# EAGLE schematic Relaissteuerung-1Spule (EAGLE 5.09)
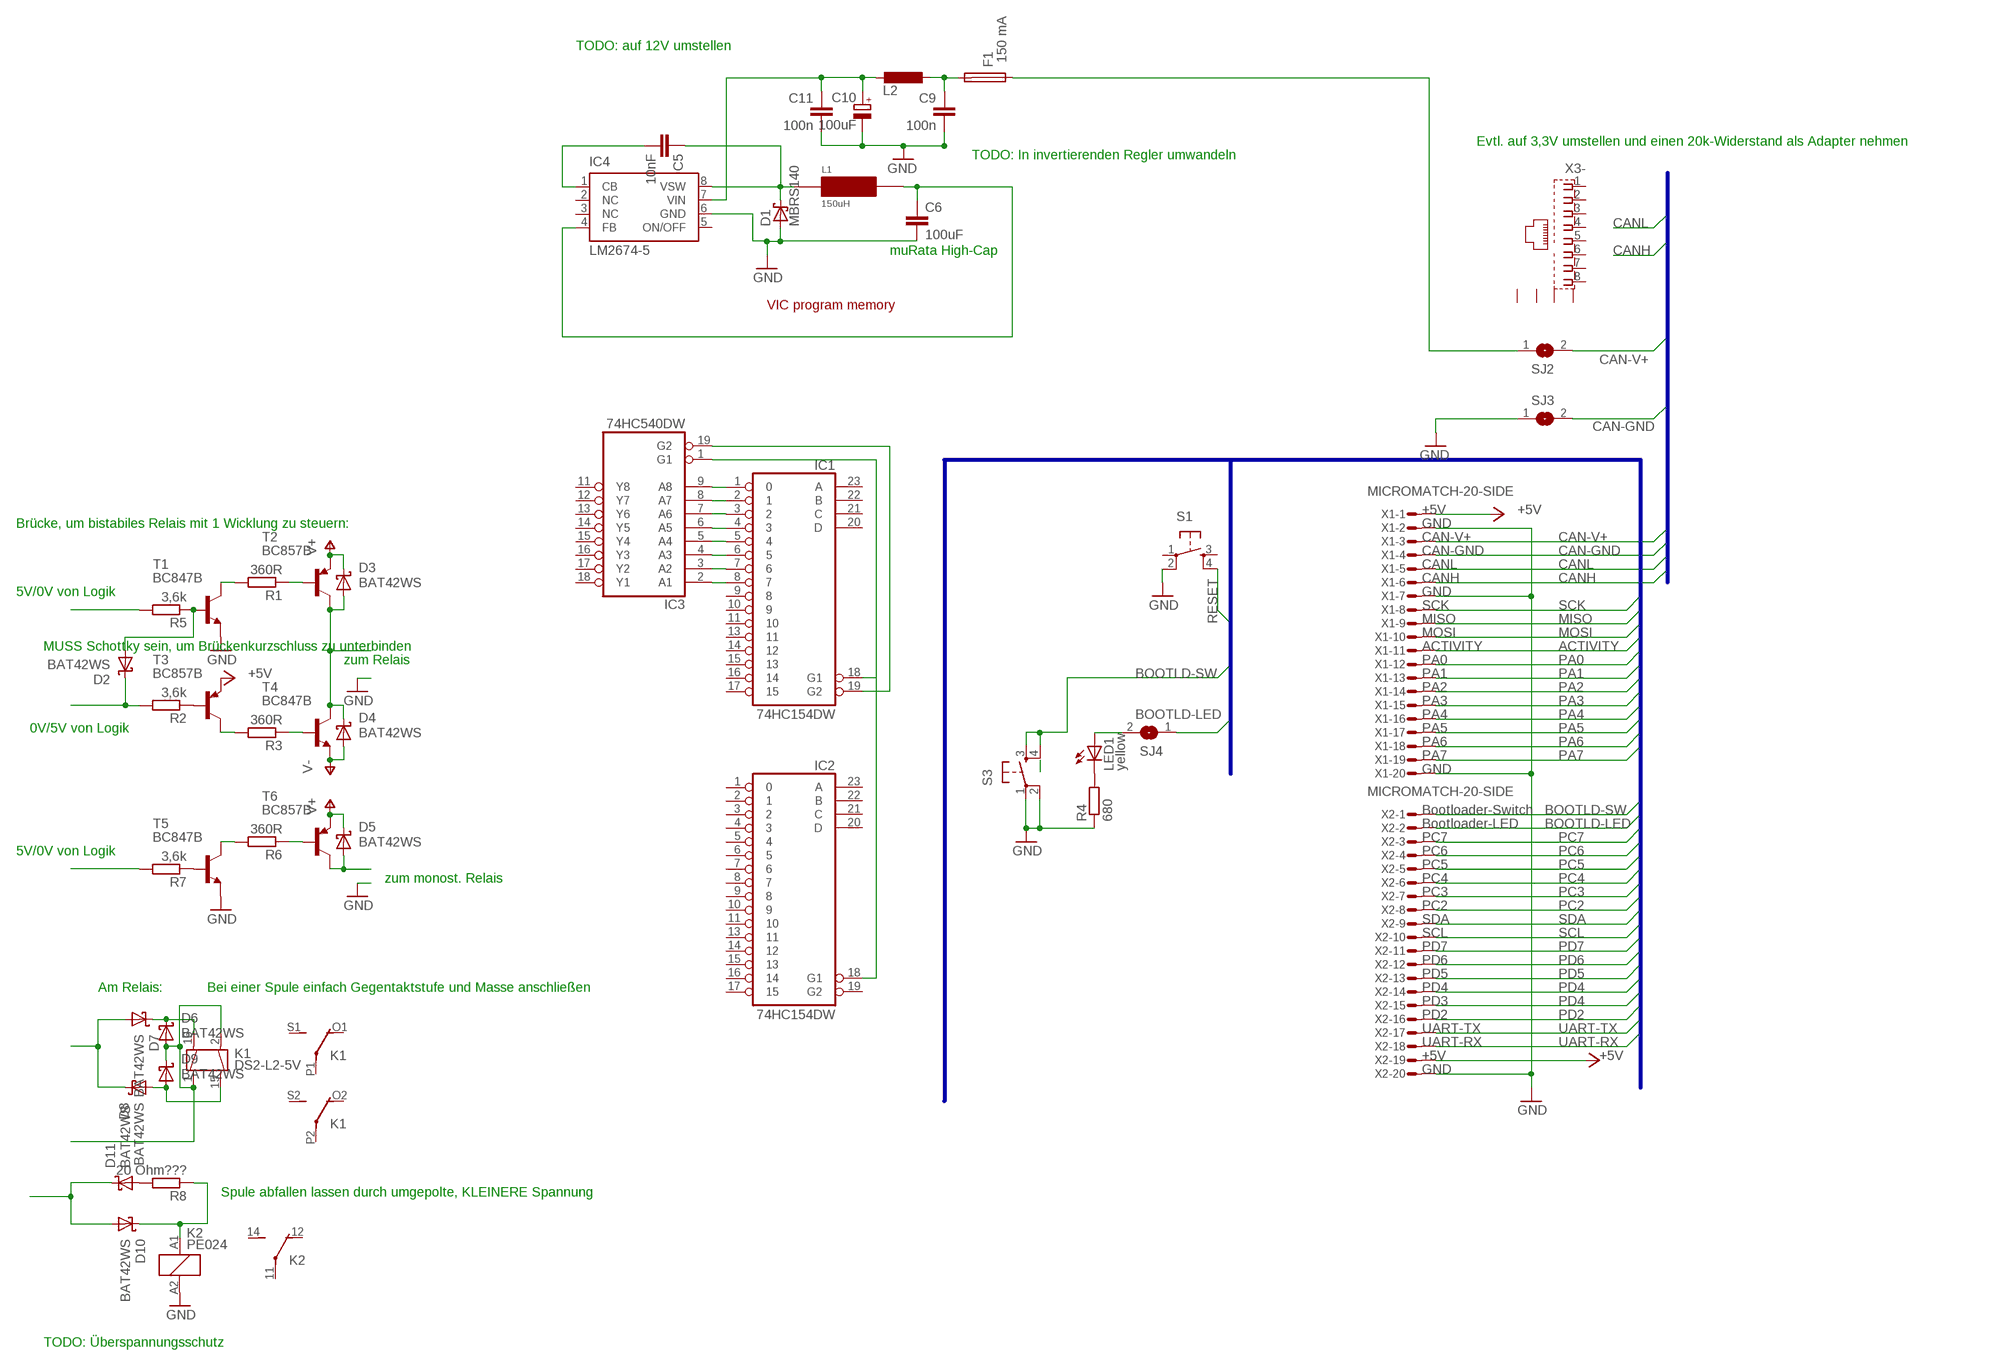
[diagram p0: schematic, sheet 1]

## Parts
C5  10nF  C-EUC0805  [C0805]
C6  100uF  C-EUC1206  [C1206]
C9  100n  C-EUC0805  [C0805]
C10  100uF  CPOL-EUD  [PANASONIC_D]
C11  100n  C-EUC0805  [C0805]
D1  MBRS140  MBRS130LT3  [SMB]
D2  BAT42WS  SCHOTTKY-SOD323W  [SOD323-W]
D3  BAT42WS  SCHOTTKY-SOD323W  [SOD323-W]
D4  BAT42WS  SCHOTTKY-SOD323W  [SOD323-W]
D5  BAT42WS  SCHOTTKY-SOD323W  [SOD323-W]
D6  BAT42WS  SCHOTTKY-SOD323W  [SOD323-W]
D7  BAT42WS  SCHOTTKY-SOD323W  [SOD323-W]
D8  BAT42WS  SCHOTTKY-SOD323W  [SOD323-W]
D9  BAT42WS  SCHOTTKY-SOD323W  [SOD323-W]
D10  BAT42WS  SCHOTTKY-SOD323W  [SOD323-W]
D11  BAT42WS  SCHOTTKY-SOD323W  [SOD323-W]
F1  150 mA  SICHERUNG-SMD  [SMD-HASF]
IC1  74HC154DW  [SO24W]
IC2  74HC154DW  [SO24W]
IC3  74HC540DW  [SO20W]
IC4  LM2674-5  LM2674  [SO8]
K1  DS2-L2-5V  [DS2E-L2]
K2  PE024  [PE]
L1  150uH  SPULEN-PIS28XX  [L-PIS28XX]
L2  L-EUL3216C  [L3216C]
LED1  yellow  LEDSMT1206  [1206]
R1  360R  R-EU_R0805  [R0805]
R2  3,6k  R-EU_R0805  [R0805]
R3  360R  R-EU_R0805  [R0805]
R4  680  R-EU_R0805  [R0805]
R5  3,6k  R-EU_R0805  [R0805]
R6  360R  R-EU_R0805  [R0805]
R7  3,6k  R-EU_R0805  [R0805]
R8  20 Ohm???  R-EU_R0805  [R0805]
S1  LSG  [SCHURTER_LSG]
S3  LSG  [SCHURTER_LSG]
SJ2  SJ  [SJ]
SJ3  SJ  [SJ]
SJ4  SJ  [SJ]
T1  BC847B  BC847  [SOT23]
T2  BC857B  BC857B-PNP-SOT23-BEC  [SOT23-BEC]
T3  BC857B  BC857B-PNP-SOT23-BEC  [SOT23-BEC]
T4  BC847B  BC847  [SOT23]
T5  BC847B  BC847  [SOT23]
T6  BC857B  BC857B-PNP-SOT23-BEC  [SOT23-BEC]
X1  MICROMATCH-20-SIDE  [MICROMATCH-20-SIDE]
X2  MICROMATCH-20-SIDE  [MICROMATCH-20-SIDE]
X3  RJ45  [RJ45]

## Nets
+5V: T3.E X1.1 X2.19
ACTIVITY: X1.11
BOOTLD-LED: SJ4.1 X2.2
BOOTLD-SW: S3.3(S) S3.4(S1) X2.1
CAN-GND [Power]: SJ3.2 X1.4
CAN-V+ [Power]: SJ2.2 X1.3
CANH: X1.6
CANL: X1.5
GND: C6.2 C9.2 C10.- C11.2 D1.A IC4.6(GND) K2.A2 R4.1 S1.2(P1) S3.1(P) S3.2(P1) SJ3.1 T1.2(E) T5.2(E) X1.2 X1.7 X1.20 X2.20
MISO: X1.9
MOSI: X1.10
N$2: C5.1 D1.C IC4.8(VSW) L1.1
N$3: C6.1 IC4.4(FB) L1.2
N$4 [Power]: F1.1 SJ2.1
N$5 [Power]: C9.1 F1.2 L2.1
N$6: LED1.C R4.2
N$7: C5.2 IC4.1(CB)
N$8 [Power]: C10.+ C11.1 IC4.7(VIN) L2.2
N$9: LED1.A SJ4.2
N$10: IC1.1 IC3.9(A8)
N$11: IC1.2 IC3.8(A7)
N$12: IC1.3 IC3.7(A6)
N$13: IC1.4 IC3.6(A5)
N$14: IC1.5 IC3.5(A4)
N$15: IC1.6 IC3.4(A3)
N$16: IC1.7 IC3.3(A2)
N$17: IC1.8 IC3.2(A1)
N$18: IC1.18(G1) IC2.18(G1) IC3.1(G1)
N$19: IC1.19(G2) IC3.19(G2)
N$20: R3.1 T4.1(B)
N$21: D2.A R5.1 T1.1(B)
N$22: R1.1 T2.B
N$23: R2.1 T3.B
N$24: R1.2 T1.3(C)
N$25: R3.2 T3.C
N$26: D3.A D4.C T2.C T4.3(C)
N$27: D6.C D7.C K1.16
N$28: D2.C R2.2
N$29: R5.2
N$30: D8.A D9.A K1.15
N$31: D6.A D9.C K1.1 K1.2
N$32: D7.A D8.C
N$33: D11.A R8.2
N$34: R7.1 T5.1(B)
N$35: R6.1 T6.B
N$36: R6.2 T5.3(C)
N$37: D5.A T6.C
N$38: R7.2
N$39: D10.A D11.C
N$40: D10.C K2.A1 R8.1
PA0: X1.12
PA1: X1.13
PA2: X1.14
PA3: X1.15
PA4: X1.16
PA5: X1.17
PA6: X1.18
PA7: X1.19
PC2: X2.8
PC3: X2.7
PC4: X2.6
PC5: X2.5
PC6: X2.4
PC7: X2.3
PD2: X2.16
PD3: X2.15
PD4: X2.14
PD5: X2.13
PD6: X2.12
PD7: X2.11
RESET: S1.4(S1)
SCK: X1.8
SCL: X2.10
SDA: X2.9
UART-RX: X2.18
UART-TX: X2.17
V+: D3.C D5.C T2.E T6.E
V-: D4.A T4.2(E)
Unconnected: IC1.9 IC1.10 IC1.11 IC1.13 IC1.14 IC1.15 IC1.16 IC1.17 IC1.20(D) IC1.21(C) IC1.22(B) IC1.23(A) IC2.1 IC2.2 IC2.3 IC2.4 IC2.5 IC2.6 IC2.7 IC2.8 IC2.9 IC2.10 IC2.11 IC2.13 IC2.14 IC2.15 IC2.16 IC2.17 IC2.19(G2) IC2.20(D) IC2.21(C) IC2.22(B) IC2.23(A) IC3.11(Y8) IC3.12(Y7) IC3.13(Y6) IC3.14(Y5) IC3.15(Y4) IC3.16(Y3) IC3.17(Y2) IC3.18(Y1) IC4.2(NC) IC4.3(NC) IC4.5(ON/OFF) K1.O1(2:O) K1.O2(3:O) K1.P1(2:P) K1.P2(3:P) K1.S1(2:S) K1.S2(3:S) K2.11(2:P) K2.12(2:O) K2.14(2:S) S1.1(P) S1.3(S) X3.1 X3.2 X3.3 X3.4 X3.5 X3.6 X3.7 X3.8 X3.G1 X3.G2 X3.G3 X3.G4

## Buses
PA[0..7],PC[2..7],PD[2..7],SCK,MISO,MOSI,CAN-CS,BOOTLD-SW,CAN-INT,BOOTLD-LED,ACTIVITY,SDA,SCL,UART-RX,UART-TX,CLK,RESET
CANL,CANH,CAN-V+,CAN-GND

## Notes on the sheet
- TODO: auf 12V umstellen
- Evtl. auf 3,3V umstellen und einen 20k-Widerstand als Adapter nehmen
- TODO: In invertierenden Regler umwandeln
- muRata High-Cap
- VIC program memory
- +5V
- Brücke, um bistabiles Relais mit 1 Wicklung zu steuern: | GND
- CAN-V+
- CAN-GND
- CANL
- CANH
- 5V/0V von Logik | GND
- SCK
- MISO
- MOSI
- MUSS Schottky sein, um Brückenkurzschluss zu unterbinden | ACTIVITY
- zum Relais | PA0
- PA1
- PA2
- PA3
- PA4
- 0V/5V von Logik | PA5
- PA6
- PA7
- GND
- Bootloader-Switch
- Bootloader-LED
- PC7
- 5V/0V von Logik | PC6
- PC5
- zum monost. Relais | PC4
- PC3
- PC2
- SDA
- SCL
- PD7
- PD6
- PD5
- Am Relais: | Bei einer Spule einfach Gegentaktstufe und Masse anschließen | PD4
- PD3
- PD2
- UART-TX
- UART-RX
- +5V
- GND
- Spule abfallen lassen durch umgepolte, KLEINERE Spannung
- TODO: Überspannungsschutz

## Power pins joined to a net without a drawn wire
GND: IC1.12(GND) IC2.12(GND) IC3.10(GND)
VCC: IC1.24(VCC) IC2.24(VCC) IC3.20(VCC)

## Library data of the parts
C5 C6 C9 C11 = rcl:C-EU: CAPACITOR, European symbol
C10 = rcl:CPOL-EU: POLARIZED CAPACITOR, European symbol
D1 = diode:MBRS130LT3: Schottky Power Rectifier
D2-D11 = 11my-ICs:SCHOTTKY-
F1 = 11my-RCA:SICHERUNG: Fuse
IC1 IC2 = 74xx-eu:74*154: 4-line to 16-line data SELECTOR/MULTIPLEXER
IC3 = 74xx-eu:74*540: Octal BUFFER and LINE DRIVER, 3-state
IC4 = lm2674-auml.se:LM2674
K1 = relay:DS2-L2-*: RELAY NAiS bistable, 2 x switch, 4 A/250 V
K2 = relay:PE*: Miniature PCB Relay 1 pole 5 A SCHRACK Source: http://www.schrack.com/.. 5807.pdf Miniature PCB Relay bistable 1pole 5 A, polarized bistable version Source: http://www.schrack.com/.. 5808.pdf
L1 = 11my-RCA:SPULEN: SMD-Power-Induktivitten
L2 = rcl:L-EU: INDUCTOR, European symbol
LED1 = led:LED: LED
R1-R8 = rcl:R-EU_: RESISTOR, European symbol
S1 S3 = 11my-mechanics:LSG: Schurter LSG SMD-Taster
SJ2-SJ4 = jumper:SJ: SMD solder JUMPER
T1 T4 T5 = transistor:BC847: NPN TRANSISTOR
T2 T3 T6 = transistor:*-PNP-: PNP Transistror
X1 X2 = apbteam_con-amp-micromatch:MICROMATCH-20: Micro-MaTch 20 Straight connector: Suited for both, female and male.
X3 = con-appsys:RJ45: AMP connector

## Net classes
0 default: width 0.15 mm
1 Power: width 0.5 mm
